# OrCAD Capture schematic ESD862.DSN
size A
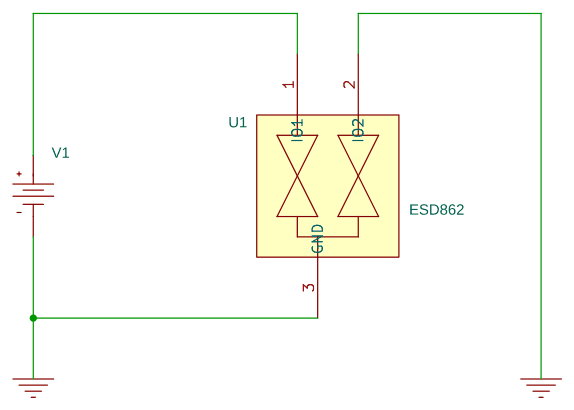
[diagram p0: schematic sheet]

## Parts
U1  ESD862
V1  VDC

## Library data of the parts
U1 = ESD862
V1 = VDC

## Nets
0: U1.2(IO2) U1.3(GND) V1.1(-)
N00133: U1.1(IO1) V1.0(+)
